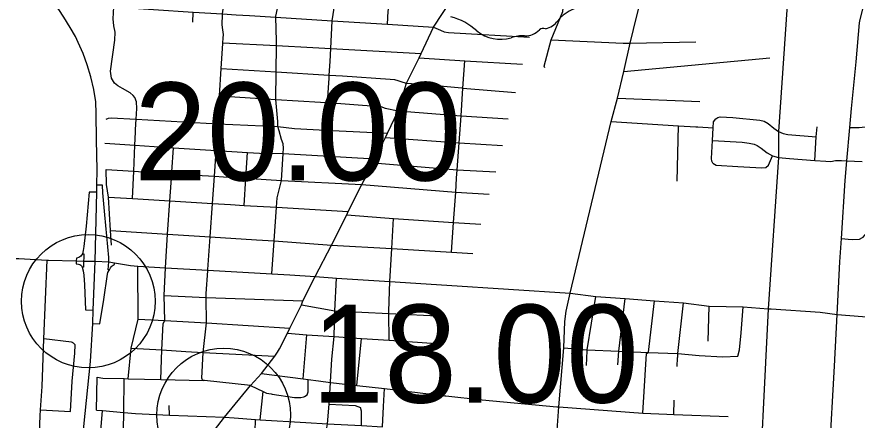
# Model space of a CAD drawing. Extents: x 1729596 to 1934326, y 644115 to 911751.
# Drawn here: x 1831865 to 1841311, y 727307 to 731839 of the extents above; entities that cross this region are included whole.
import ezdxf

# ---------------------------------------------------------------- set-up
doc = ezdxf.new("R2010")
doc.units = 0
for name, color, linetype in [('Default', 7, 'Continuous'), ('GM_X_City_Street', 7, 'Continuous'), ('GM_X_Interchange_Ramps', 7, 'Continuous'), ('GM_X_Interstate_Route', 7, 'Continuous'), ('GM_X_State_Route', 7, 'Continuous'), ('GM_X_State_Shield', 7, 'Continuous'), ('GM_X_Township', 7, 'Continuous')]:
    doc.layers.add(name, color=color, linetype=linetype)

msp = doc.modelspace()

# ---------------------------------------------------------------- linework, layer by layer
at = {"layer": 'Default'}
for centre in [(1832669.2, 728643.7), (1834190.6, 727366)]:
    msp.add_circle(centre, 750, dxfattribs=at)
at = {"layer": 'GM_X_City_Street'}
for points in [[(1836033.4, 731755), (1836039.2, 731902), (1836072.4, 732064.5), (1836065.7, 732334.3), (1836085.5, 732656.6), (1836090.2, 732732.7), (1836106.6, 732989.1), (1836113.2, 733090.8), (1836126.2, 733287.5), (1836139.6, 733491.4), (1836144.1, 733559.5), (1836176.6, 733856.6)], [(1837699.8, 723889.1), (1837865.7, 726077.4), (1837890.5, 726480.3), (1837932, 727088.4), (1837957.5, 727455.7), (1838012.8, 728121.9), (1838023.3, 728414.9), (1838041.1, 728532.8), (1838085.5, 728733.1), (1838544.6, 730661.9), (1838616.8, 730926.8), (1838689.5, 731223.5), (1838760.5, 731544.6), (1838835.4, 731848.7), (1838908.9, 732151.4), (1838982.9, 732452.6), (1839052.8, 732752.9), (1839130, 733059.1), (1839198.3, 733338.4), (1839279.9, 733667.4)], [(1837799.6, 731265.7), (1837792.3, 731284.1), (1837869.8, 731579.1), (1838002.3, 731898.2), (1838028.9, 732184.7), (1838107.3, 732483.2), (1838184.5, 732777.1), (1838260.6, 733066.9), (1838331.8, 733337.9)], [(1840995.2, 724829.6), (1840980.5, 724875.5), (1840972, 725066.3), (1840946.1, 726012.2), (1841000.6, 726916.8), (1841055.9, 727915.8), (1841085.4, 728496.4), (1841116.7, 729088.1), (1841133.2, 729348.7), (1841174.5, 729999.7), (1841194.4, 730219.3), (1841228.4, 730595), (1841247.8, 730808.6), (1841297.5, 731333.1), (1841337.9, 731772), (1841339.6, 731789.6), (1841448.2, 732231.1), (1841496, 733028.8)], [(1834013, 728986.3), (1834013.5, 728992.2), (1834014, 729001.1), (1834039.2, 729366.9), (1834065.1, 729742.3), (1834086, 730047), (1834105.5, 730329.4), (1834106, 730337.8), (1834124.7, 730636), (1834144.5, 730950), (1834164, 731259.9), (1834181.6, 731538.7), (1834182.2, 731546.7), (1834186.5, 731598.8), (1834187.1, 731639), (1834179.8, 731691.3), (1834174.6, 731747.6), (1834178.4, 731865.9), (1834178.6, 731871.9), (1834222, 732181.4), (1834203.4, 732527.9)], [(1833192.8, 730931.9), (1833173.6, 730954.8), (1833140.8, 730986.1), (1833052.5, 731033.8), (1832999.5, 731064), (1832962.6, 731093.5), (1832928.7, 731149), (1832917.8, 731229.6), (1832965.7, 731578.3), (1832971, 731665.7), (1832956.7, 731737), (1832947.8, 731817.3), (1832955, 731952.8), (1832963.9, 732058.1), (1832981.7, 732254.2), (1832977.9, 732279.1)], [(1834732.7, 728950.2), (1834757.6, 729320.9), (1834782.9, 729698.9), (1834790.1, 729805.6), (1834838.6, 729999.8), (1834858.3, 730304.1), (1834862.5, 730365.1), (1834859.7, 730410.8), (1834838.9, 730459.3), (1834815.4, 730557.6), (1834800.2, 730607.5), (1834800.2, 730662.8), (1834777.6, 730911.5), (1834780.2, 731221.9), (1834782.7, 731515.3), (1834783.1, 731570.4), (1834778.1, 731834.7), (1834777.9, 731845.3), (1834839.3, 732145.4)], [(1835374.8, 731152.8), (1835377, 731185.1), (1835387.2, 731335.8), (1835394.9, 731482.6), (1835411.2, 731794.5), (1835459.6, 732108)], [(1832955, 731952.8), (1833848.1, 731890.8), (1834178.6, 731871.9), (1834331.6, 731863.1), (1834479.5, 731853.7), (1834778.1, 731834.7), (1835411.2, 731794.5), (1836033.4, 731755), (1836550.4, 731722.2)], [(1833842.8, 731780), (1833847.8, 731885.8), (1833848.1, 731890.8)], [(1836550.4, 731722.2), (1836627.7, 731689.4), (1836667, 731669.8), (1836716.8, 731661.8), (1837626.7, 731609.5)], [(1841228.4, 730595), (1841331, 730597.1), (1841401.2, 730603), (1841413.9, 730607.2), (1841461.9, 730623.2), (1841527.1, 730661.3), (1841572.4, 730704.1), (1841573.8, 730707.2), (1841591.8, 730747.6), (1841605.8, 730817.3), (1841707.8, 731740.7)], [(1834182.2, 731546.7), (1834782.7, 731515.3), (1835191, 731494), (1835394.9, 731482.6), (1836410.3, 731426.1)], [(1837869.8, 731579.1), (1838681.7, 731541.9), (1838708.1, 731542.8)], [(1838708.1, 731542.8), (1838760.5, 731544.6), (1839498.7, 731559)], [(1836386.1, 731376.8), (1836900.9, 731345.4), (1837548.7, 731305.8)], [(1836750.4, 729195.6), (1836774, 729530), (1836798, 729870.3), (1836809, 730025.9), (1836815.5, 730118.7), (1836836.7, 730423.4), (1836857.8, 730726.7), (1836879.5, 731039.1), (1836900.9, 731345.4)], [(1838689.5, 731223.5), (1840329.4, 731379.5)], [(1834164, 731259.9), (1834780.2, 731221.9), (1835377, 731185.1), (1835527.3, 731175.8), (1836060.9, 731138.5), (1836110.9, 731134.5), (1836146.6, 731125.1), (1836204, 731106.7), (1836246.9, 731093.3), (1836415.5, 731082.3), (1836866.8, 731040.2), (1836879.5, 731039.1), (1837470, 730988.1)], [(1835334.9, 730564.9), (1835356, 730875.4), (1835374.6, 731149.7), (1835374.8, 731152.8)], [(1833207.5, 730689.5), (1833214.1, 730810.8), (1833209, 730885.2), (1833192.8, 730931.9)], [(1834144.5, 730950), (1834777.6, 730911.5), (1835279.2, 730880.9), (1835356, 730875.4), (1835900.8, 730836.1), (1835956.7, 730829.8), (1836006.1, 730813.9), (1836152.8, 730781.4), (1836857.8, 730726.7), (1837386.4, 730694.7)], [(1838616.8, 730926.8), (1839540.5, 730887.6)], [(1832870.5, 730688.1), (1832895.1, 730701.2), (1832925.4, 730706), (1833207.5, 730689.5), (1834124.7, 730636), (1834800.2, 730607.5), (1834985, 730585.8), (1835334.9, 730564.9), (1836031.7, 730532)], [(1833166.3, 729796.5), (1833180, 730103.4), (1833193, 730396.3), (1833199.6, 730544.7), (1833201.1, 730571.7), (1833207.5, 730689.5)], [(1839689.7, 730194.5), (1839676.8, 730218.2), (1839673.3, 730247.7), (1839683, 730449.2), (1839691, 730591.7), (1839696.9, 730659.1), (1839722.9, 730694.6)], [(1839722.9, 730694.6), (1839744.2, 730707.6), (1839769, 730714.6), (1839914.4, 730706.4), (1840217.4, 730679.7), (1840263.6, 730665.9), (1840311.1, 730642.1), (1840374.9, 730589.6), (1840426.2, 730550.9), (1840479.9, 730528.4), (1840530, 730515.9), (1840850.1, 730489.6)], [(1838544.6, 730661.9), (1839301.6, 730614.2), (1839496.4, 730604.7)], [(1839288.9, 729992.7), (1839301.6, 730614.2)], [(1839496.4, 730604.7), (1839520.9, 730603.5), (1839691, 730591.7)], [(1840833.9, 730224.5), (1840850.1, 730489.6), (1840858.9, 730603.4)], [(1832853.9, 730418.1), (1833193, 730396.3), (1833625.6, 730368.6), (1834106, 730337.8), (1834457.4, 730315.3), (1834591.3, 730306.8), (1834858.3, 730304.1), (1835888, 730243.4)], [(1836010.2, 730482.9), (1836836.7, 730423.4), (1837323.5, 730394.5)], [(1839683, 730449.2), (1840018.3, 730430.2), (1840096.1, 730420.8), (1840151.1, 730407.1), (1840187.4, 730392.1), (1840231.1, 730363.3), (1840297.4, 730310.8), (1840359.9, 730277), (1840424.9, 730257), (1840550, 730247), (1840833.9, 730224.5), (1840957.6, 730215.8), (1841012.7, 730213.2), (1841066.4, 730223.2), (1841133.3, 730224.3), (1841194.4, 730219.3)], [(1833606, 730076.9), (1833607.5, 730098.9), (1833625.6, 730368.6)], [(1834422, 729720.8), (1834440.1, 730024.9), (1834457.4, 730315.3)], [(1839689.7, 730194.5), (1839725.9, 730172), (1839970.1, 730158.6), (1840238.6, 730140.7), (1840282.4, 730145.7), (1840313.6, 730172), (1840359.9, 730277)], [(1841194.4, 730219.3), (1841367.8, 730213.2)], [(1832870.4, 730122.7), (1833180, 730103.4), (1833606, 730076.9), (1834086, 730047), (1834391.9, 730028), (1834440.1, 730024.9), (1834838.6, 729999.8), (1835743, 729953.5), (1836798, 729870.3), (1837172.7, 729845)], [(1832929.2, 729273.5), (1832919.8, 729438.9), (1832894.4, 729812.9), (1832873.1, 729954.7), (1832870.4, 730122.7)], [(1835873.3, 730198), (1836815.5, 730118.7), (1837248.3, 730098.7)], [(1833510.4, 728394.6), (1833528.5, 728428.5), (1833522.1, 728708.9), (1833534.8, 729020.1), (1833560.2, 729397.8), (1833585.4, 729771.2), (1833606, 730076.9)], [(1841133.2, 729348.7), (1841207.5, 729342), (1841263.3, 729336.3), (1841335.6, 729342.2), (1841368.5, 729360.6), (1841376.3, 729365), (1841413.7, 729410), (1841438, 729485.4), (1841445.3, 729597.5), (1841445.4, 729621.5), (1841445.6, 729739.8), (1841450, 729819.8), (1841465.5, 729871.5)], [(1832894.4, 729812.9), (1833166.3, 729796.5), (1833585.4, 729771.2), (1834065.1, 729742.3), (1834266, 729730.2), (1834422, 729720.8), (1834782.9, 729698.9), (1835590.2, 729652.2)], [(1835573.2, 729616), (1835999.9, 729580.9), (1836099.8, 729574.4), (1836774, 729530), (1837081.4, 729509.8)], [(1836044.8, 728504.9), (1836045.9, 728533.8), (1836058.2, 728867.2), (1836080, 729237.6), (1836099.8, 729574.4)], [(1832919.8, 729438.9), (1833560.2, 729397.8), (1834039.2, 729366.9), (1834559.2, 729333.5), (1834757.6, 729320.9), (1835403.2, 729274.8), (1836080, 729237.6), (1836750.4, 729195.6), (1836990.3, 729180.5)], [(1831859.1, 729125), (1831886.7, 729123.1), (1832207.6, 729104.1), (1832222.4, 729103.7)], [(1832097.7, 726606.2), (1832127.5, 727355), (1832132, 727425.2), (1832148.9, 727687.2), (1832170.9, 728219.8), (1832207.6, 729104.1)], [(1832222.4, 729103.7), (1832534.2, 729096.1), (1832616.2, 729095.3)], [(1832616.2, 729095.3), (1832746.3, 729094), (1832898.7, 729088), (1832963.2, 729076.5), (1833119, 729048.7)], [(1833117.1, 727773.6), (1833151.3, 728117.8), (1833228.4, 728443.9), (1833224, 729039.2)], [(1833119, 729048.7), (1833144.6, 729044.1), (1833224, 729039.2), (1833534.8, 729020.1), (1834013.5, 728992.2), (1834732.7, 728950.2), (1834934, 728938.6)], [(1833973.1, 727753.2), (1833963, 727754.3), (1833955, 727758.4), (1833951, 727760.5), (1833945.3, 727780.6), (1833960.5, 728069.2), (1833997.9, 728399.3), (1833993.1, 728685.6), (1833995.5, 728731.3), (1834013, 728986.3)], [(1834934, 728938.6), (1835216.9, 728922.3), (1835414.5, 728905)], [(1835391, 727736.9), (1835407.3, 727992.5), (1835431.2, 728247.9), (1835438.8, 728534.7), (1835460.1, 728901.1)], [(1835414.5, 728905), (1835460.1, 728901.1), (1836058.2, 728867.2), (1836696.8, 728825)], [(1836696.8, 728825), (1838085.5, 728733.1), (1838373, 728697.5), (1838703.2, 728676.2), (1839034.3, 728649.7), (1839358.5, 728626.1), (1839646.4, 728589.6), (1840028.1, 728581.3), (1840309, 728558.8), (1840344.1, 728556.5)], [(1833522.1, 728708.9), (1833993.1, 728685.6), (1835081.8, 728647.4)], [(1838276.7, 728088.7), (1838277.1, 728096.2), (1838373, 728697.5)], [(1835063.8, 728603), (1835438.8, 728534.7), (1836044.8, 728504.9), (1836671.7, 728474.2)], [(1838621.3, 727928.2), (1838630.2, 728082.1), (1838703.2, 728676.2)], [(1838960.6, 728069.4), (1838965.5, 728072.9), (1839034.3, 728649.7)], [(1839292.6, 728006.9), (1839293.3, 728018.2), (1839295.4, 728055.6), (1839358.5, 728626.1)], [(1839637.3, 728194.3), (1839646.4, 728589.6)], [(1839970.3, 728026.9), (1839988.7, 728099.4), (1840005.9, 728288.7), (1840028.1, 728581.3)], [(1840344.1, 728556.5), (1840895.9, 728519.8), (1841085.4, 728496.4), (1841703.1, 728444.7), (1842555.9, 728384.6)], [(1833228.4, 728443.9), (1833528.5, 728428.5), (1833997.9, 728399.3), (1834935.3, 728342.5)], [(1836049.1, 728207), (1836044.8, 728504.9)], [(1833483.6, 727765), (1833497.1, 728095.8), (1833509.2, 728392.4), (1833510.4, 728394.6)], [(1834906.2, 728283.1), (1835124.7, 728268), (1835431.2, 728247.9), (1835738.1, 728226.5), (1836049.1, 728207), (1836631.3, 728166.9)], [(1835083.5, 727773), (1835124.7, 728268)], [(1835686.6, 727697.8), (1835738.1, 728226.5)], [(1832492.5, 728178.2), (1832479.1, 728183.1), (1832170.9, 728219.8)], [(1832467.1, 727405.6), (1832488.7, 727745.8), (1832515.7, 728059.7), (1832520.4, 728153.8), (1832502.9, 728174.4), (1832493.4, 728177.8), (1832492.5, 728178.2)], [(1833151.3, 728117.8), (1833497.1, 728095.8), (1833766.9, 728078.7), (1833960.5, 728069.2), (1834764.4, 728027.1)], [(1838012.8, 728121.9), (1838277.1, 728096.2), (1838630.2, 728082.1), (1838959.9, 728069), (1839295.4, 728055.6), (1839532.7, 728035.5), (1839800.7, 728020.8), (1839970.3, 728026.9)], [(1838266.7, 727920.9), (1838276.6, 728087.7), (1838276.7, 728088.7)], [(1838899.9, 727387.3), (1838941, 728055.6), (1838959.9, 728069), (1838960.6, 728069.4)], [(1839287.1, 727909.5), (1839292.6, 728006.9)], [(1832761.7, 727421.4), (1832768.2, 727790)], [(1832768.2, 727790), (1832831.9, 727780.2), (1833071.4, 727774.7), (1833117.1, 727773.6), (1833483.6, 727765), (1833963, 727754.3)], [(1833066.4, 727201.1), (1833068.1, 727393.1), (1833071.4, 727774.7)], [(1834492.5, 727697.7), (1833973.1, 727753.2)], [(1834614.3, 727833.4), (1835083.5, 727773), (1835140.3, 727764.8), (1835254.3, 727748.2), (1835390.7, 727732.3), (1835686.6, 727697.8), (1835996.1, 727661.6), (1836090, 727650.6), (1836676.7, 727582.7)], [(1835098.1, 727572.8), (1835129.9, 727593.4), (1835138.8, 727627.2), (1835140.3, 727764.8)], [(1834492.5, 727697.7), (1834633.5, 727629.5), (1834670.1, 727610.3), (1834722.9, 727602.2), (1834734.4, 727600.4)], [(1834670.8, 726087.6), (1834684.5, 726284.9), (1834694.7, 726362.8), (1834718.9, 726440.3), (1834749.6, 726500.8), (1834754.9, 726511.4), (1834867.7, 726604.5), (1834943.7, 726671.3), (1835068.8, 726781.2), (1835142.8, 726841.9), (1835206, 726893.7), (1835270.8, 726990), (1835306.6, 727053.2), (1835337.5, 727154.5), (1835358.8, 727266.6), (1835375.1, 727488), (1835390.7, 727732.3), (1835390.9, 727736.7), (1835391, 727736.9)], [(1835976.1, 727232.8), (1835986.6, 727461.1), (1835996.1, 727661.6)], [(1834599.5, 727310.6), (1834633.5, 727629.5)], [(1834734.4, 727600.4), (1834986.8, 727561.3), (1835058.9, 727561.3), (1835092.4, 727570.9), (1835097.2, 727572.3), (1835098.1, 727572.8)], [(1836676.7, 727582.7), (1836685.9, 727581.6), (1837097.2, 727534.1), (1837935.2, 727457.8)], [(1833582.5, 727362.8), (1833577.5, 727470.6)], [(1835375.1, 727488), (1835668.7, 727472), (1835728.1, 727450.3)], [(1839249.8, 727370.9), (1839254.3, 727531.6)], [(1832132, 727425.2), (1832467.1, 727405.6)], [(1832761.7, 727421.4), (1832826.8, 727415.4), (1833068.1, 727393.1), (1833198.8, 727381.1), (1833582.5, 727362.8), (1834199.5, 727340.6), (1834308.9, 727332.1)], [(1832793.6, 727008.4), (1832793.6, 727008.4), (1832826.8, 727415.4)], [(1835738, 727245.8), (1835740.9, 727407.8), (1835728.1, 727450.3)], [(1837935.2, 727457.8), (1837957.5, 727455.7), (1838899.9, 727387.3), (1839169.8, 727373.6), (1839249.8, 727370.9), (1839859.5, 727350.2)], [(1834308.9, 727332.1), (1834549.8, 727313.4), (1834599.5, 727310.6), (1835114.9, 727280.7), (1835358.8, 727266.6), (1835738, 727245.8), (1835976.1, 727232.8)], [(1834443.3, 726855.3), (1834448.7, 726931), (1834466.1, 726982.6), (1834516.6, 727067.4), (1834536.6, 727099.8), (1834539.7, 727104.8), (1834545.8, 727180.8), (1834549.8, 727313.4)]]:
    msp.add_lwpolyline(points, dxfattribs=at)
at = {"layer": 'GM_X_Interchange_Ramps'}
for points in [[(1832898.7, 729088), (1832899.2, 729136.5), (1832855.7, 729615.4), (1832833.2, 729862.1), (1832827, 729948.9), (1832765.6, 729948.4)], [(1832763.8, 729868.2), (1832678.7, 729867.5), (1832644.2, 729487.8), (1832617.7, 729257.5), (1832612.9, 729213.4), (1832603.8, 729175.6), (1832585, 729150.4), (1832562.5, 729136.9), (1832536.1, 729126.9), (1832534.2, 729096.1)], [(1832603.8, 729175.6), (1832617.8, 729174.4), (1832617.3, 729132.2), (1832616.2, 729095.3)], [(1832534.2, 729096.1), (1832532.3, 729065.3), (1832560, 729060.3), (1832572.4, 729056.5), (1832585.5, 729049.5), (1832593, 729042.2), (1832601.1, 729025.1), (1832609.4, 728986.8), (1832617.7, 728935.6), (1832624.8, 728829.4), (1832636.2, 728546.7), (1832725.3, 728542.1)], [(1832616.2, 729095.3), (1832616.5, 729059.8), (1832616.7, 729025.4), (1832601.1, 729025.1)], [(1832718.8, 728393.8), (1832799.1, 728389.7), (1832843.2, 728664.7), (1832885.2, 728946.5), (1832890.3, 728964.9), (1832899.3, 728985.6), (1832906.2, 728996.4), (1832917.4, 729020.2), (1832928, 729032.8), (1832936.8, 729041.5), (1832947.9, 729048.7), (1832962, 729055.5), (1832963.2, 729076.5)], [(1832906.2, 728996.4), (1832892.8, 728997.4), (1832895.8, 729040.5), (1832898.7, 729088)]]:
    msp.add_lwpolyline(points, dxfattribs=at)
at = {"layer": 'GM_X_Interstate_Route'}
for points in [[(1832746.3, 729094), (1832763.8, 729868.2), (1832765.6, 729948.4), (1832769.2, 730119.3), (1832761.8, 730456.8), (1832758.5, 730752.1), (1832752, 730883.3), (1832729.9, 731023.1), (1832696.9, 731163.4), (1832655.7, 731300.8), (1832611.7, 731427.3), (1832554, 731551.1), (1832523.7, 731617), (1832463.3, 731718.8), (1832394.6, 731837), (1832339.6, 731919.5), (1832221.4, 732070.7), (1832133.4, 732169.7), (1832045.5, 732252.2), (1831981.2, 732309.5), (1831918.8, 732370.1), (1831739.3, 732505.1)], [(1832568.8, 726587.2), (1832620.3, 727237.8), (1832693.2, 727966.9), (1832718.8, 728393.8), (1832725.3, 728542.1), (1832746.3, 729094)]]:
    msp.add_lwpolyline(points, dxfattribs=at)
at = {"layer": 'GM_X_State_Route'}
for points in [[(1835216.9, 728922.3), (1835403.2, 729274.8), (1835573.2, 729616), (1835590.2, 729652.2), (1835743, 729953.5), (1835873.3, 730198), (1835888, 730243.4), (1836010.2, 730482.9), (1836031.7, 730532), (1836152.8, 730781.4), (1836246.9, 731093.3), (1836386.1, 731376.8), (1836410.3, 731426.1), (1836550.4, 731722.2), (1836745.2, 732018.1)], [(1832822.3, 725645.5), (1832861.9, 725693.4), (1833250.9, 726203), (1833413.1, 726371.3), (1833533.8, 726519.4), (1833928.4, 727014.7), (1834048.3, 727145.3), (1834199.5, 727340.6), (1834492.5, 727697.7), (1834614.3, 727833.4), (1834764.4, 728027.1), (1834796.8, 728072.5), (1834818.3, 728109.9), (1834906.2, 728283.1), (1834935.3, 728342.5), (1835063.8, 728603), (1835081.8, 728647.4), (1835216.9, 728922.3)]]:
    msp.add_lwpolyline(points, dxfattribs=at)
at = {"layer": 'GM_X_State_Shield'}
for centre, radius, start, end in [((1838267.4, 731548.4), 404.5, 94.40312, 142.57675), ((1836580.9, 731192.3), 667.2, 47.18416, 75.83597), ((1837755, 731936.9), 238.6, 282.87319, 323.27711), ((1837302.5, 732009.3), 423.3, 230.70037, 286.29184), ((1837547.1, 731278.7), 347.9, 85.69512, 111.20995), ((1837578, 731851), 225.6, 268.77702, 315.54927), ((1837782, 731646.4), 63.5, 65.75173, 132.64842)]:
    msp.add_arc(centre, radius, start, end, dxfattribs=at)
at = {"layer": 'GM_X_Township'}
msp.add_lwpolyline([(1841095.2, 741263.6), (1840912.9, 738651.1), (1840826.6, 736667.4), (1840795.9, 736258.9), (1840795.9, 736228.2), (1840773.9, 735881.2), (1840769.5, 735835.1), (1840749.1, 735536.8), (1840730.2, 735173.2), (1840703.8, 734834.1), (1840688.2, 734520.5), (1840667.5, 734207), (1840649.4, 733893.5), (1840625.4, 733578), (1840602.7, 733155.6), (1840520.1, 731919.3), (1840426.2, 730550.9), (1840424.9, 730257), (1840309, 728558.8), (1840185.8, 726071.2)], dxfattribs=at)

# ---------------------------------------------------------------- texts
at = {"layer": 'Default'}
for s, p in [('20.00', (1833184.2, 730000.5)), ('18.00', (1835175.5, 727504.8))]:
    msp.add_text(s, height=1100, dxfattribs=at).set_placement(p)

doc.saveas('drawing.dxf')
